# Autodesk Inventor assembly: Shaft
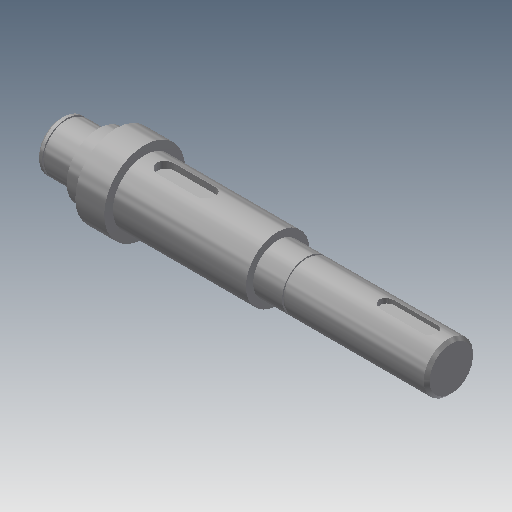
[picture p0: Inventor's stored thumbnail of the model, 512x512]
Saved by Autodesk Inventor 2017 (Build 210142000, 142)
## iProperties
Created: 2019-02
Part Number: Shaft
Document SubType Name: Assembly
Designer: user
Mass: 329.535 g
Surface Area: 97.9427 cm^2
Volume: 41.979 cm^3
Density: 7.85 g/cm^3
ClientObjectVersion: 1
Author: user
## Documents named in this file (2)
- C:\Users\user\Documents\EIA\Cursos\Diseño asistido por computador\Clase 7 Dynamic simulation\Ensamble reductor de velocidad\Ensamble\Design Accelerator\Shaft1.iam
- C:\Users\user\Documents\EIA\Cursos\Diseño asistido por computador\Clase 7 Dynamic simulation\Ensamble reductor de velocidad\Ensamble\Design Accelerator\Shaft1.ipt
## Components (1 placed, 1 different names)
1. Shaft:1
